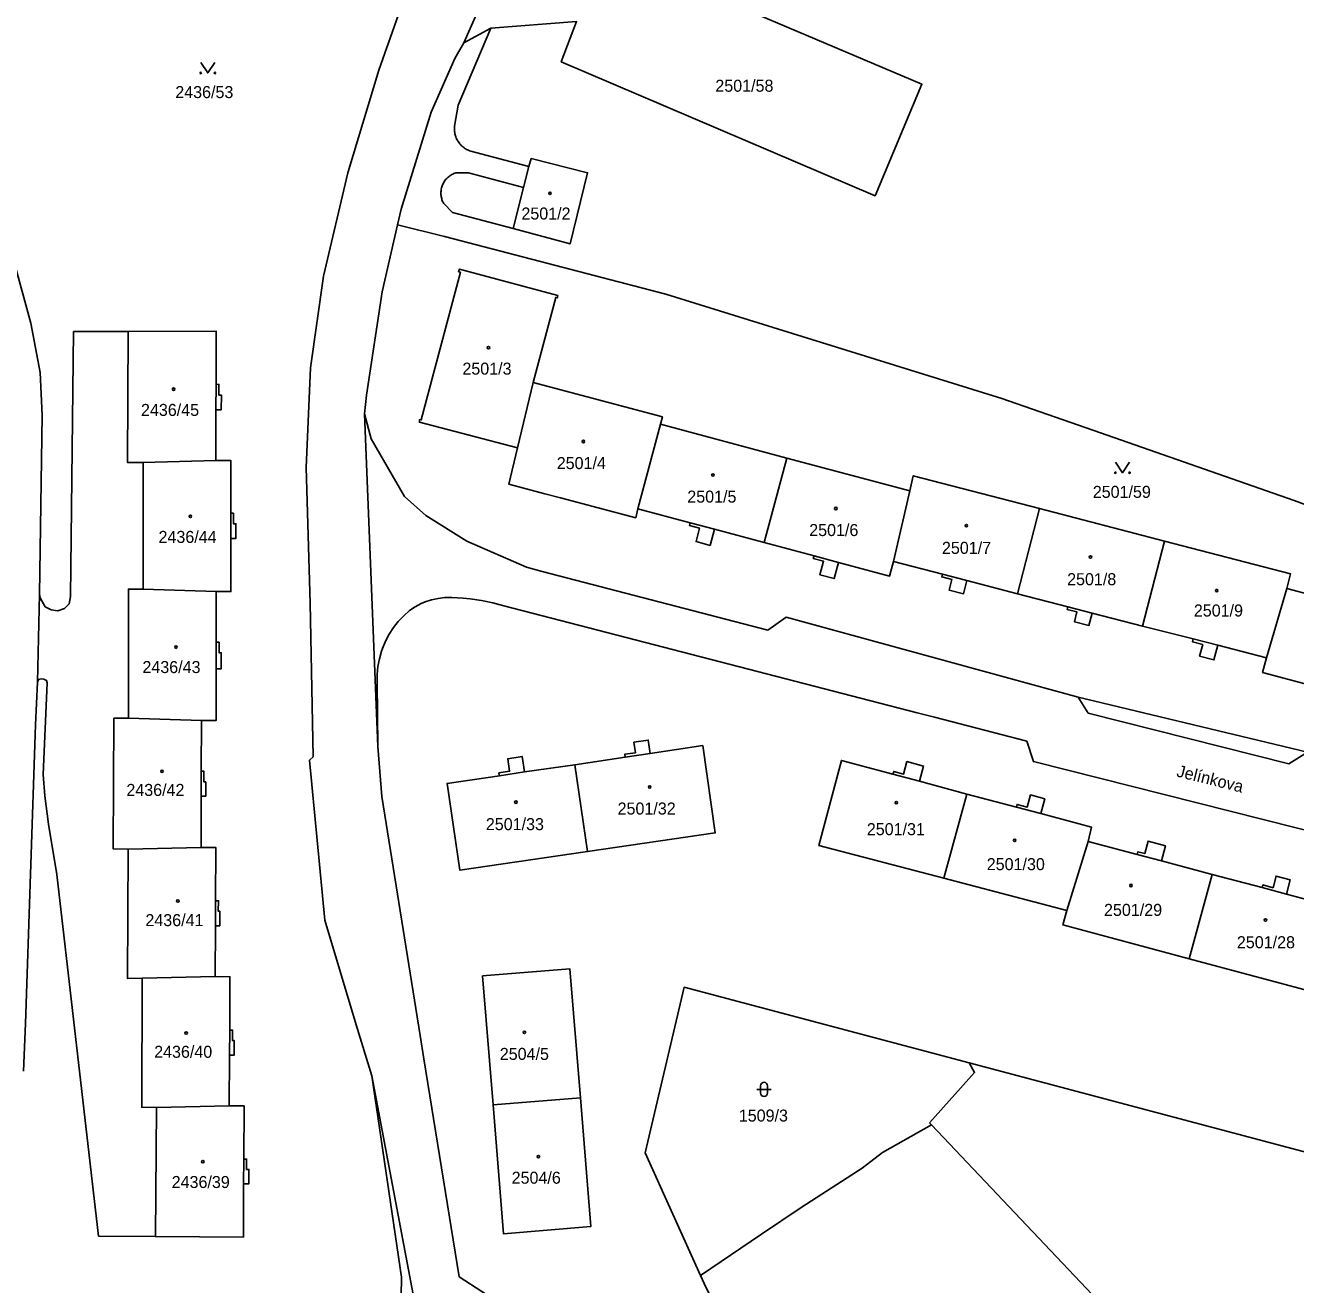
# Model space of a CAD drawing. Extents: x -869103 to -863415, y -1015889 to -1012477.
# Drawn here: x -865773 to -865593.3, y -1015265.4 to -1015087.3 of the extents above; entities that cross this region are included whole.
import ezdxf

# ---------------------------------------------------------------- set-up
doc = ezdxf.new("R2010")
doc.units = 0
for name, color, linetype in [('Hranice parcel', 7, 'Continuous'), ('Parcelní čísla', 7, 'Continuous'), ('Pop  PČ popisy', 7, 'Continuous'), ('Vnitřní kresba', 7, 'Continuous'), ('Značky budov', 7, 'Continuous'), ('Značky kultur', 7, 'Continuous')]:
    doc.layers.add(name, color=color, linetype=linetype)

msp = doc.modelspace()

# ---------------------------------------------------------------- linework, layer by layer
at = {"layer": 'Hranice parcel'}
for p, q in [((-865701.64, -1015068.66), (-865710.97, -1015089.75)), ((-865720.34, -1015115.51), (-865719.83, -1015113.26)), ((-865722.51, -1015124.98), (-865720.34, -1015115.51)), ((-865703.35, -1015147.05), (-865701.17, -1015137.81)), ((-865723.15, -1015189.3), (-865725, -1015142.2)), ((-865686.33, -1015155.68), (-865683.16, -1015143.68)), ((-865665.27, -1015148.47), (-865683.16, -1015143.68)), ((-865746.06, -1015148.8), (-865756.34, -1015149.11)), ((-865668.45, -1015160.43), (-865665.27, -1015148.47)), ((-865647.86, -1015153.12), (-865665.27, -1015148.47)), ((-865756.34, -1015149.11), (-865756.32, -1015167.03)), ((-865650.17, -1015163.12), (-865647.86, -1015153.12)), ((-865629.52, -1015155.62), (-865632.64, -1015167.66)), ((-865611.81, -1015160.21), (-865629.52, -1015155.62)), ((-865614.93, -1015172.24), (-865611.81, -1015160.21)), ((-865597.42, -1015176.72), (-865594.52, -1015166.95)), ((-865577.04, -1015171.53), (-865594.52, -1015166.95)), ((-865746.01, -1015167.36), (-865756.32, -1015167.03)), ((-865723.15, -1015189.3), (-865723.23, -1015180.2)), ((-865748.09, -1015185.59), (-865758.39, -1015185.26)), ((-865695.28, -1015191.85), (-865693.48, -1015204.12)), ((-865639.79, -1015196), (-865643.04, -1015207.89)), ((-865622.65, -1015202.7), (-865625.66, -1015212.49)), ((-865748.15, -1015203.56), (-865758.46, -1015203.79)), ((-865643.04, -1015207.89), (-865625.66, -1015212.49)), ((-865605.08, -1015207.36), (-865608.34, -1015219.32)), ((-865608.34, -1015219.32), (-865590.7, -1015224.03)), ((-865746.15, -1015221.83), (-865756.46, -1015222.07)), ((-865472.95, -1015278.17), (-865639.47, -1015234.02)), ((-865744.15, -1015240.1), (-865754.46, -1015240.34)), ((-865706.83, -1015239.97), (-865694.47, -1015238.96)), ((-865645.1, -1015242.51), (-865644.8, -1015242.8)), ((-865644.8, -1015242.8), (-865611.29, -1015278.14)), ((-865685.3, -1015246.76), (-865677.46, -1015264.1)), ((-865668.83, -1015258.27), (-865677.46, -1015264.1))]:
    msp.add_line(p, q, dxfattribs=at)
for points in [[(-865684.62, -1015013.75), (-865692.03, -1015025.34), (-865703.54, -1015046.35), (-865708.92, -1015057.7), (-865713.03, -1015067.04), (-865718.28, -1015080.23), (-865722.99, -1015093.61), (-865727.39, -1015108.12), (-865730.84, -1015122.74), (-865732.64, -1015135.71), (-865733.27, -1015149.79), (-865732.7, -1015169.02), (-865732.27, -1015190.73), (-865732.79, -1015191.22), (-865730.64, -1015213.84), (-865726.22, -1015228.66), (-865723.96, -1015235.88), (-865719.79, -1015264.35), (-865719.9, -1015269.7), (-865721.09, -1015273.66), (-865722.88, -1015276.62), (-865723.53, -1015277.07)], [(-865710.97, -1015089.75), (-865707.13, -1015087.68), (-865695.01, -1015086.74), (-865697.19, -1015092.41), (-865652.77, -1015111.37), (-865646.15, -1015095.6), (-865690.91, -1015076.58), (-865692.68, -1015080.66), (-865699.65, -1015071.07), (-865701.64, -1015068.66)], [(-865719.83, -1015113.26), (-865715.58, -1015099.54), (-865712.26, -1015091.97), (-865710.97, -1015089.75)], [(-865701.46, -1015106.1), (-865701.76, -1015107.26), (-865702.5, -1015110.22), (-865703.98, -1015116.03), (-865695.9, -1015118.17), (-865693.46, -1015108.12), (-865701.46, -1015106.1)], [(-865720.34, -1015115.51), (-865713.72, -1015117.14), (-865682.39, -1015125.3), (-865634.83, -1015140.04)], [(-865774.59, -1015120.76), (-865772.23, -1015129.42), (-865770.9, -1015136.36), (-865770.61, -1015142.42), (-865771, -1015167.74), (-865771.28, -1015180.19), (-865771.55, -1015186.19), (-865772.99, -1015228.46), (-865773.27, -1015235.2)], [(-865701.17, -1015137.81), (-865697.96, -1015125.75), (-865697.74, -1015125.81), (-865697.65, -1015125.48), (-865711.6, -1015121.75), (-865711.7, -1015122.13), (-865711.45, -1015122.19), (-865716.98, -1015143.09), (-865717.22, -1015143.03), (-865717.24, -1015143.41), (-865703.35, -1015147.05)], [(-865725, -1015142.2), (-865724.72, -1015139.6), (-865722.51, -1015124.98)], [(-865746.06, -1015148.8), (-865746.03, -1015141.65), (-865745.28, -1015141.65), (-865745.27, -1015139.58), (-865745.62, -1015139.58), (-865745.62, -1015138.05), (-865746.02, -1015138.04), (-865745.99, -1015130.54), (-865758.45, -1015130.56), (-865758.53, -1015149.12), (-865756.34, -1015149.11)], [(-865683.16, -1015143.68), (-865682.88, -1015142.64), (-865701.17, -1015137.81)], [(-865634.83, -1015140.04), (-865620.89, -1015144.92), (-865593.5, -1015154.46), (-865572.18, -1015162.34), (-865533.8, -1015176.2), (-865532.38, -1015177.3), (-865532.07, -1015179.63)], [(-865725, -1015142.2), (-865724.06, -1015145.75), (-865719.38, -1015153.92), (-865716.33, -1015156.59), (-865710.56, -1015160.21)], [(-865703.35, -1015147.05), (-865704.61, -1015152.17), (-865699.5, -1015153.52), (-865697.28, -1015154.1), (-865686.64, -1015156.91), (-865686.33, -1015155.68)], [(-865746.01, -1015167.36), (-865743.92, -1015167.36), (-865743.93, -1015159.84), (-865743.2, -1015159.84), (-865743.2, -1015157.76), (-865743.56, -1015157.76), (-865743.56, -1015156.28), (-865743.93, -1015156.28), (-865743.94, -1015148.8), (-865746.06, -1015148.8)], [(-865629.52, -1015155.62), (-865647.37, -1015150.99), (-865647.86, -1015153.12)], [(-865686.33, -1015155.68), (-865678.93, -1015157.65), (-865679.03, -1015158.03), (-865677.6, -1015158.41), (-865678.11, -1015160.3), (-865676.12, -1015160.83), (-865675.52, -1015158.55), (-865668.45, -1015160.43)], [(-865710.56, -1015160.21), (-865702.08, -1015163.91), (-865699.88, -1015164.51), (-865667.95, -1015172.82), (-865665.38, -1015170.97), (-865624.04, -1015182.32), (-865591.61, -1015190.09), (-865554.86, -1015199.35)], [(-865668.45, -1015160.43), (-865661.42, -1015162.31), (-865661.52, -1015162.7), (-865660.07, -1015163.08), (-865660.58, -1015164.99), (-865658.58, -1015165.53), (-865657.97, -1015163.23), (-865650.72, -1015165.17), (-865650.17, -1015163.12)], [(-865594.52, -1015166.95), (-865594, -1015164.87), (-865611.81, -1015160.21)], [(-865650.17, -1015163.12), (-865643.24, -1015164.92), (-865643.34, -1015165.3), (-865641.92, -1015165.67), (-865642.3, -1015167.15), (-865640.26, -1015167.68), (-865639.78, -1015165.81), (-865632.64, -1015167.66)], [(-865756.32, -1015167.03), (-865758.42, -1015167.02), (-865758.39, -1015185.26)], [(-865748.09, -1015185.59), (-865745.99, -1015185.59), (-865746, -1015178.29), (-865745.29, -1015178.29), (-865745.29, -1015176.02), (-865745.59, -1015176.02), (-865745.59, -1015174.54), (-865746, -1015174.54), (-865746.01, -1015167.36)], [(-865718.64, -1015170.04), (-865717.85, -1015169.51), (-865717.01, -1015169.06), (-865716.43, -1015168.81), (-865715.52, -1015168.52), (-865714.58, -1015168.32), (-865713.63, -1015168.22), (-865712.68, -1015168.22), (-865711.06, -1015168.3), (-865710.07, -1015168.39), (-865708.47, -1015168.62), (-865706.88, -1015168.96), (-865705.32, -1015169.39)], [(-865632.64, -1015167.66), (-865625.51, -1015169.5), (-865625.61, -1015169.89), (-865624.22, -1015170.25), (-865624.58, -1015171.64), (-865622.52, -1015172.17), (-865622.06, -1015170.4), (-865614.93, -1015172.24)], [(-865723.23, -1015180.2), (-865723.23, -1015179.09), (-865723.13, -1015177.98), (-865722.92, -1015176.89), (-865722.63, -1015175.81), (-865722.48, -1015175.4), (-865722.05, -1015174.38), (-865721.53, -1015173.39), (-865720.93, -1015172.46), (-865720.24, -1015171.59), (-865719.47, -1015170.78), (-865718.64, -1015170.04)], [(-865705.32, -1015169.39), (-865646.85, -1015184.51), (-865644.36, -1015185.14), (-865631.32, -1015188.53), (-865630.39, -1015191.42), (-865556.21, -1015210.11), (-865474.47, -1015231.93), (-865417.93, -1015246.82), (-865415.47, -1015245.07), (-865406.66, -1015247.51), (-865402.19, -1015249.8), (-865397.38, -1015253.49), (-865392.83, -1015257.55), (-865390.31, -1015257.12), (-865387.48, -1015242.46)], [(-865614.93, -1015172.24), (-865607.79, -1015174.07), (-865607.89, -1015174.46), (-865606.43, -1015174.83), (-865606.86, -1015176.5), (-865604.84, -1015177.02), (-865604.31, -1015174.96), (-865597.42, -1015176.72)], [(-865597.42, -1015176.72), (-865597.96, -1015178.83), (-865590.7, -1015180.73), (-865590.8, -1015181.11), (-865589.38, -1015181.48), (-865589.6, -1015182.33), (-865587.6, -1015182.86), (-865587.28, -1015181.62), (-865580.16, -1015183.48)], [(-865758.39, -1015185.26), (-865760.47, -1015185.27), (-865760.58, -1015203.74), (-865758.46, -1015203.79)], [(-865748.15, -1015203.56), (-865748.13, -1015196.31), (-865747.48, -1015196.31), (-865747.47, -1015194.29), (-865747.74, -1015194.29), (-865747.73, -1015192.78), (-865748.11, -1015192.78), (-865748.09, -1015185.59)], [(-865693.48, -1015204.12), (-865675.39, -1015201.5), (-865677.17, -1015189.15), (-865684.61, -1015190.25), (-865684.88, -1015188.37), (-865686.92, -1015188.67), (-865686.7, -1015190.16), (-865688.2, -1015190.38), (-865688.15, -1015190.77), (-865695.28, -1015191.85)], [(-865701.92, -1015268.74), (-865704.59, -1015268.88), (-865706.82, -1015267.42), (-865711.64, -1015264.27), (-865716.63, -1015233.44), (-865717.16, -1015230.17), (-865722.57, -1015196.34), (-865723.15, -1015189.3)], [(-865695.28, -1015191.85), (-865702.38, -1015192.88), (-865702.71, -1015190.71), (-865704.75, -1015191.01), (-865704.49, -1015192.79), (-865706, -1015193.01), (-865705.94, -1015193.41), (-865713.33, -1015194.5), (-865711.54, -1015206.77), (-865693.48, -1015204.12)], [(-865639.79, -1015196), (-865646.51, -1015194.2), (-865645.93, -1015192.04), (-865648.27, -1015191.41), (-865648.75, -1015193.19), (-865650.15, -1015192.81), (-865650.25, -1015193.2), (-865657.55, -1015191.24), (-865660.72, -1015203.26), (-865643.04, -1015207.89)], [(-865622.65, -1015202.7), (-865622.14, -1015200.68), (-865629.33, -1015198.77), (-865628.77, -1015196.66), (-865630.79, -1015196.13), (-865631.25, -1015197.85), (-865632.69, -1015197.47), (-865632.79, -1015197.86), (-865639.79, -1015196)], [(-865605.08, -1015207.36), (-865612.26, -1015205.46), (-865611.7, -1015203.33), (-865614.16, -1015202.68), (-865614.62, -1015204.42), (-865615.59, -1015204.16), (-865615.69, -1015204.55), (-865622.65, -1015202.7)], [(-865758.46, -1015203.79), (-865758.54, -1015222.11), (-865756.46, -1015222.07)], [(-865746.15, -1015221.83), (-865746.11, -1015214.64), (-865745.49, -1015214.64), (-865745.48, -1015212.59), (-865745.7, -1015212.59), (-865745.67, -1015211.09), (-865746.09, -1015211.09), (-865746.05, -1015203.57), (-865748.15, -1015203.56)], [(-865587.49, -1015212.06), (-865594.59, -1015210.16), (-865594.05, -1015208.14), (-865596.04, -1015207.61), (-865596.47, -1015209.25), (-865597.93, -1015208.86), (-865598.03, -1015209.24), (-865605.08, -1015207.36)], [(-865625.66, -1015212.49), (-865626.2, -1015214.51), (-865608.34, -1015219.32)], [(-865694.47, -1015238.96), (-865695.96, -1015220.73), (-865708.31, -1015221.74), (-865706.83, -1015239.97)], [(-865756.46, -1015222.07), (-865756.54, -1015240.31), (-865754.46, -1015240.34)], [(-865744.15, -1015240.1), (-865744.11, -1015232.96), (-865743.46, -1015232.96), (-865743.45, -1015230.88), (-865743.69, -1015230.88), (-865743.68, -1015229.39), (-865744.09, -1015229.38), (-865744.05, -1015221.84), (-865746.15, -1015221.83)], [(-865639.47, -1015234.02), (-865679.79, -1015223.33), (-865685.3, -1015246.76)], [(-865639.47, -1015234.02), (-865638.7, -1015235.38), (-865645.1, -1015242.51)], [(-865754.46, -1015240.34), (-865754.6, -1015258.59), (-865742.16, -1015258.68), (-865742.12, -1015251.16), (-865741.39, -1015251.16), (-865741.37, -1015249.11), (-865741.71, -1015249.11), (-865741.7, -1015247.63), (-865742.09, -1015247.63), (-865742.05, -1015240.11), (-865744.15, -1015240.1)], [(-865706.83, -1015239.97), (-865705.36, -1015258.2), (-865692.98, -1015257.17), (-865694.47, -1015238.96)], [(-865644.8, -1015242.8), (-865651.71, -1015246.71), (-865654.61, -1015248.92), (-865663.23, -1015254.47), (-865668.83, -1015258.27)], [(-865677.46, -1015264.1), (-865676.66, -1015265.86), (-865674.26, -1015270.59)]]:
    msp.add_lwpolyline(points, dxfattribs=at)
at = {"layer": 'Vnitřní kresba'}
for p, q in [((-865711.77, -1015098.55), (-865707.13, -1015087.68)), ((-865712.27, -1015101.51), (-865711.77, -1015098.55)), ((-865701.76, -1015107.26), (-865710.15, -1015105.01)), ((-865712.11, -1015108.13), (-865710.31, -1015108.13)), ((-865702.5, -1015110.22), (-865710.31, -1015108.13)), ((-865712.58, -1015113.76), (-865713.81, -1015112.49)), ((-865703.98, -1015116.03), (-865712.58, -1015113.76)), ((-865766.6, -1015168.06), (-865766.21, -1015130.57)), ((-865766.21, -1015130.57), (-865758.45, -1015130.56)), ((-865746.02, -1015138.04), (-865746.03, -1015141.65)), ((-865743.93, -1015156.28), (-865743.93, -1015159.84)), ((-865678.93, -1015157.65), (-865675.52, -1015158.55)), ((-865661.42, -1015162.31), (-865657.97, -1015163.23)), ((-865643.24, -1015164.92), (-865639.78, -1015165.81)), ((-865625.51, -1015169.5), (-865622.06, -1015170.4)), ((-865607.79, -1015174.07), (-865604.31, -1015174.96)), ((-865746, -1015174.54), (-865746, -1015178.29)), ((-865624.04, -1015182.32), (-865622.65, -1015184.58)), ((-865622.65, -1015184.58), (-865594.22, -1015191.71)), ((-865688.15, -1015190.77), (-865684.61, -1015190.25)), ((-865594.22, -1015191.71), (-865591.61, -1015190.09)), ((-865748.13, -1015196.31), (-865748.11, -1015192.78)), ((-865705.94, -1015193.41), (-865702.38, -1015192.88)), ((-865646.51, -1015194.2), (-865650.25, -1015193.2)), ((-865629.33, -1015198.77), (-865632.79, -1015197.86)), ((-865612.26, -1015205.46), (-865615.69, -1015204.55)), ((-865762.67, -1015258.53), (-865768.54, -1015207.4)), ((-865594.59, -1015210.16), (-865598.03, -1015209.24)), ((-865746.09, -1015211.09), (-865746.11, -1015214.64)), ((-865744.09, -1015229.38), (-865744.11, -1015232.96)), ((-865718, -1015267.53), (-865723.96, -1015235.88)), ((-865742.09, -1015247.63), (-865742.12, -1015251.16)), ((-865762.67, -1015258.53), (-865754.6, -1015258.59))]:
    msp.add_line(p, q, dxfattribs=at)
for points in [[(-865710.15, -1015105.01), (-865710.3, -1015104.95), (-865710.44, -1015104.89), (-865710.58, -1015104.81), (-865710.71, -1015104.73), (-865710.85, -1015104.65), (-865710.97, -1015104.56), (-865711.1, -1015104.46), (-865711.22, -1015104.35), (-865711.33, -1015104.25), (-865711.44, -1015104.13), (-865711.54, -1015104.01), (-865711.64, -1015103.89), (-865711.73, -1015103.76), (-865711.82, -1015103.63), (-865711.89, -1015103.49), (-865711.97, -1015103.35), (-865712.03, -1015103.21), (-865712.09, -1015103.06), (-865712.14, -1015102.91), (-865712.18, -1015102.76), (-865712.22, -1015102.61), (-865712.25, -1015102.45), (-865712.27, -1015102.3), (-865712.29, -1015102.14), (-865712.29, -1015101.98), (-865712.29, -1015101.82), (-865712.29, -1015101.67), (-865712.27, -1015101.51)], [(-865713.81, -1015112.49), (-865713.88, -1015112.35), (-865713.95, -1015112.22), (-865714.01, -1015112.08), (-865714.06, -1015111.93), (-865714.1, -1015111.78), (-865714.14, -1015111.64), (-865714.17, -1015111.48), (-865714.19, -1015111.33), (-865714.2, -1015111.18), (-865714.21, -1015111.03), (-865714.21, -1015110.87), (-865714.19, -1015110.72), (-865714.18, -1015110.57), (-865714.15, -1015110.42), (-865714.12, -1015110.27), (-865714.08, -1015110.12), (-865714.03, -1015109.98), (-865713.97, -1015109.83), (-865713.91, -1015109.69), (-865713.84, -1015109.56), (-865713.76, -1015109.42), (-865713.68, -1015109.3), (-865713.59, -1015109.17), (-865713.49, -1015109.05), (-865713.39, -1015108.94), (-865713.29, -1015108.83), (-865713.17, -1015108.73), (-865713.05, -1015108.63), (-865712.93, -1015108.54), (-865712.8, -1015108.45), (-865712.67, -1015108.37), (-865712.54, -1015108.3), (-865712.4, -1015108.24), (-865712.26, -1015108.18), (-865712.11, -1015108.13)], [(-865766.6, -1015168.06), (-865766.82, -1015169.09), (-865767.45, -1015169.76), (-865768.4, -1015170.08), (-865769.35, -1015169.95), (-865770.19, -1015169.51), (-865770.92, -1015168.23), (-865771, -1015167.74)], [(-865771.28, -1015180.19), (-865771.13, -1015179.82), (-865770.75, -1015179.72), (-865770.38, -1015179.75), (-865770.01, -1015179.93), (-865769.92, -1015180.29), (-865770.47, -1015193.26), (-865770.23, -1015196.26), (-865769.71, -1015200.25), (-865768.54, -1015207.4)]]:
    msp.add_lwpolyline(points, dxfattribs=at)
at = {"layer": 'Značky budov'}
for centre in [(-865698.78, -1015111.03), (-865707.48, -1015132.86), (-865752.03, -1015138.73), (-865694.05, -1015146.14), (-865675.73, -1015150.88), (-865658.33, -1015155.61), (-865749.66, -1015156.73), (-865639.86, -1015158.05), (-865622.3, -1015162.48), (-865604.44, -1015167.22), (-865751.7, -1015175.22), (-865753.67, -1015192.78), (-865684.66, -1015195.01), (-865703.6, -1015197.15), (-865649.78, -1015197.21), (-865633.03, -1015202.55), (-865616.58, -1015208.94), (-865751.43, -1015211.12), (-865597.54, -1015213.82), (-865750.25, -1015229.81), (-865702.39, -1015229.72), (-865747.89, -1015248.01), (-865700.41, -1015247.3)]:
    msp.add_circle(centre, 0.175, dxfattribs=at)
at = {"layer": 'Značky kultur'}
for p, q in [((-865669.49, -1015237.78), (-865667.49, -1015237.78)), ((-865668.99, -1015237.28), (-865668.99, -1015238.28)), ((-865667.99, -1015238.28), (-865667.99, -1015237.28))]:
    msp.add_line(p, q, dxfattribs=at)
for points in [[(-865748.19, -1015092.51), (-865747.19, -1015094.01), (-865746.19, -1015092.51)], [(-865618.77, -1015149.06), (-865617.77, -1015150.56), (-865616.77, -1015149.06)]]:
    msp.add_lwpolyline(points, dxfattribs=at)
for centre in [(-865748.19, -1015094.01), (-865746.19, -1015094.01), (-865618.77, -1015150.56), (-865616.77, -1015150.56)]:
    msp.add_circle(centre, 0.1, dxfattribs=at)
for centre, start, end in [((-865668.49, -1015237.28), 0, 180), ((-865668.49, -1015238.28), 180, 359.9879)]:
    msp.add_arc(centre, 0.5, start, end, dxfattribs=at)

# ---------------------------------------------------------------- texts
at = {"layer": 'Parcelní čísla'}
for s, p in [('2501/58', (-865675.38, -1015096.66)), ('2436/53', (-865751.79, -1015097.56)), ('2501/2', (-865702.82, -1015114.74)), ('2501/3', (-865711.17, -1015136.68)), ('2436/45', (-865756.64, -1015142.52)), ('2501/4', (-865697.82, -1015150.04)), ('2501/59', (-865621.98, -1015154.11)), ('2501/5', (-865679.35, -1015154.78)), ('2501/6', (-865662.1, -1015159.51)), ('2436/44', (-865754.16, -1015160.48)), ('2501/7', (-865643.32, -1015162.03)), ('2501/8', (-865625.61, -1015166.46)), ('2501/9', (-865607.68, -1015170.89)), ('2436/43', (-865756.44, -1015178.89)), ('2436/42', (-865758.71, -1015196.27)), ('2501/32', (-865689.21, -1015198.9)), ('2501/33', (-865707.85, -1015201.11)), ('2501/31', (-865653.95, -1015201.82)), ('2501/30', (-865636.98, -1015206.77)), ('2501/29', (-865620.39, -1015213.24)), ('2436/41', (-865756.02, -1015214.69)), ('2501/28', (-865601.59, -1015217.81)), ('2436/40', (-865754.78, -1015233.31)), ('2504/5', (-865705.88, -1015233.61)), ('1509/3', (-865672.06, -1015242.33)), ('2504/6', (-865704.2, -1015251.12)), ('2436/39', (-865752.3, -1015251.73))]:
    msp.add_text(s, height=1.7, dxfattribs=at).set_placement(p)
at = {"layer": 'Pop  PČ popisy'}
msp.add_text('Jelínkova', height=1.7, rotation=346, dxfattribs=at).set_placement((-865610.23, -1015193.5))

doc.saveas('drawing.dxf')
